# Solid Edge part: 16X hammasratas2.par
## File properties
Author: Türk
Template: Iso Part.par
Last saved by: Türk
Revision: 3
Application: Solid Edge
Accuracy: 0,990
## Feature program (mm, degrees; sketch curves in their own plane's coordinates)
pattern "PatternOccurrence_5"  XOffset = 22.5 deg
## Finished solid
Body 1: solid body, 68 faces, 194 edges, 128 vertices.
  Faces by surface: plane 51, cylinder 17
  Edges by curve: line 144, circle 34, intersection 16
Bounding box of the edges (mm): 26.000 x 36.000 x 26.000, from (-13, 0, -13) to (13, 36, 13).
Cylindrical faces by radius (mm): R6 x1, R11 x16
Planar faces by outward normal: +x 1, +y 2, +z 1, -x 1, -y 1, -z 1, oblique 44
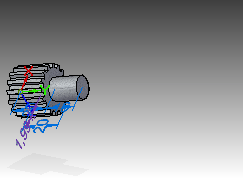
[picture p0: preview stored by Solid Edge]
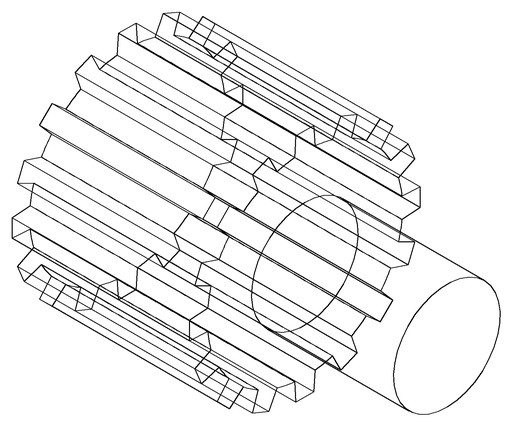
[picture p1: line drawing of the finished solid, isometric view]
